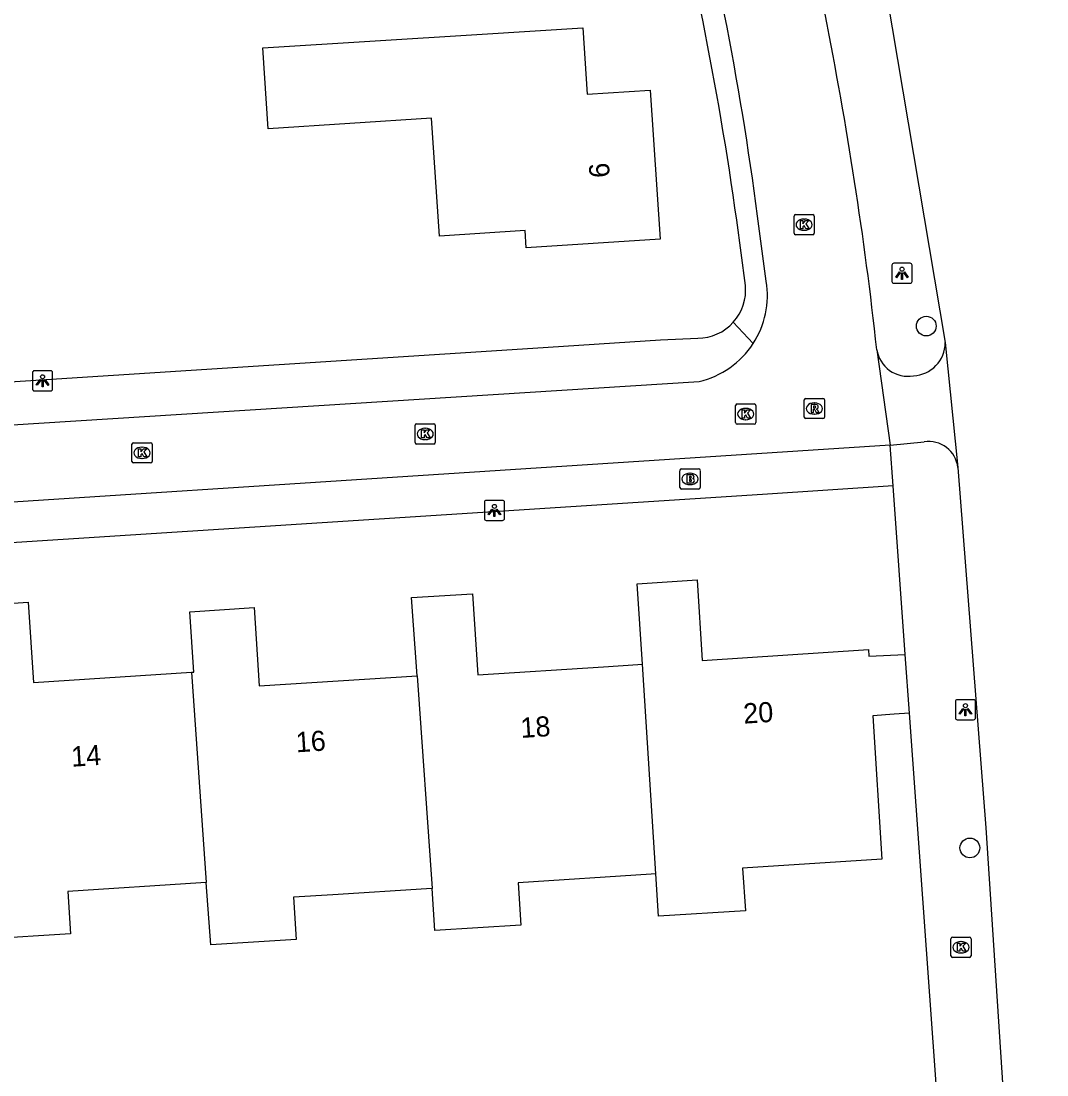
# Model space of a CAD drawing. Extents: x 159628 to 160723, y 388176 to 389416.
# Drawn here: x 160671.2 to 160722.1, y 388404.8 to 388457.1 of the extents above; entities that cross this region are included whole.
import ezdxf

# ---------------------------------------------------------------- set-up
doc = ezdxf.new("R2010")
doc.units = 0
for name, color, linetype in [('IMGEO_Boom', 7, 'Continuous'), ('IMGEO_Brandkraan', 7, 'Continuous'), ('IMGEO_Fietspad_gesloten', 7, 'Continuous'), ('IMGEO_Fietspad_open', 7, 'Continuous'), ('IMGEO_Kolk', 7, 'Continuous'), ('IMGEO_Lichtpunt', 7, 'Continuous'), ('IMGEO_Muur', 7, 'Continuous'), ('IMGEO_Pand', 7, 'Continuous'), ('IMGEO_Pand_nummerreeks', 7, 'Continuous'), ('IMGEO_Rijbaan_lokaal_open', 7, 'Continuous'), ('IMGEO_Rioolput', 7, 'Continuous'), ('IMGEO_Voetpad_open', 7, 'Continuous')]:
    doc.layers.add(name, color=color, linetype=linetype)

msp = doc.modelspace()

# ---------------------------------------------------------------- linework, layer by layer
at = {"layer": 'IMGEO_Boom'}
for centre in [(160716.092, 388441.932), (160718.25, 388416.067)]:
    msp.add_circle(centre, 0.489, dxfattribs=at)
at = {"layer": 'IMGEO_Brandkraan'}
for p, q in [((160703.883, 388433.931), (160703.883, 388434.783)), ((160703.958, 388434.857), (160704.81, 388434.857)), ((160704.371, 388434.637), (160704.396, 388434.637)), ((160704.884, 388434.783), (160704.884, 388433.931)), ((160704.394, 388434.077), (160704.369, 388434.077)), ((160704.81, 388433.857), (160703.958, 388433.857))]:
    msp.add_line(p, q, dxfattribs=at)
for points in [[(160703.883, 388433.931), (160703.883, 388434.783)], [(160703.958, 388434.857), (160704.81, 388434.857)], [(160704.231, 388434.557), (160704.231, 388434.157), (160704.444, 388434.157)], [(160704.462, 388434.557), (160704.231, 388434.557)], [(160704.41, 388434.476), (160704.356, 388434.476), (160704.356, 388434.4)], [(160704.356, 388434.4), (160704.409, 388434.4)], [(160704.884, 388434.783), (160704.884, 388433.931)], [(160704.418, 388434.324), (160704.356, 388434.324), (160704.356, 388434.243)], [(160704.356, 388434.243), (160704.418, 388434.243)], [(160704.81, 388433.857), (160703.958, 388433.857)]]:
    msp.add_lwpolyline(points, dxfattribs=at)
for centre, radius, start, end in [((160703.96, 388434.781), 0.0765, 91.552, 178.448), ((160703.96, 388434.781), 0.0765, 91.552, 178.448), ((160704.411, 388434.438), 0.0379, 267.8285, 90.9355), ((160704.466, 388434.412), 0.145, 59.4692, 91.5367), ((160704.491, 388434.459), 0.0922, 285.5137, 58.1501), ((160704.808, 388434.781), 0.0765, 1.552, 88.448), ((160704.808, 388434.781), 0.0765, 1.552, 88.448), ((160703.96, 388433.933), 0.0765, 181.552, 268.448), ((160703.96, 388433.933), 0.0765, 181.552, 268.448), ((160704.419, 388434.283), 0.0404, 269.8759, 90.5077), ((160704.45, 388434.408), 0.251, 268.6676, 293.5347), ((160704.496, 388434.267), 0.105, 301.3115, 78.989), ((160704.808, 388433.933), 0.0765, 271.552, 358.448), ((160704.808, 388433.933), 0.0765, 271.552, 358.448)]:
    msp.add_arc(centre, radius, start, end, dxfattribs=at)
for centre, major_axis, ratio, start_param, end_param in [((160704.37, 388434.357), (-0.387, 0.002), 0.722429, 4.712389, 7.853982), ((160704.395, 388434.357), (-0.39, 0.002), 0.717154, 1.570796, 4.712389)]:
    msp.add_ellipse(centre, major_axis=major_axis, ratio=ratio, start_param=start_param, end_param=end_param, dxfattribs=at)
at = {"layer": 'IMGEO_Fietspad_gesloten'}
for points in [[(160699.145, 388509.738), (160699.188, 388509.634), (160699.94, 388507.646), (160702.623, 388500), (160705.363, 388491.619), (160707.756, 388484.312), (160713.361, 388462.92), (160717.033, 388441.112)], [(160717.033, 388441.112), (160717.655, 388434.924)], [(160717.655, 388434.924), (160719.035, 388417.059), (160722.068, 388370.816)]]:
    msp.add_lwpolyline(points, dxfattribs=at)
at = {"layer": 'IMGEO_Fietspad_open'}
msp.add_lwpolyline([(160714.306, 388436.033), (160715.985, 388436.189)], dxfattribs=at)
for centre, radius, start, end in [((160715.179, 388441.004), 1.558, 188.8561, 280.0805), ((160715.384, 388441.118), 1.649, 272.3647, 359.8038), ((160716.228, 388434.775), 1.435, 5.9549, 99.7583)]:
    msp.add_arc(centre, radius, start, end, dxfattribs=at)
at = {"layer": 'IMGEO_Kolk'}
for p, q in [((160709.611, 388447.46), (160710.463, 388447.46)), ((160709.536, 388446.534), (160709.536, 388447.386)), ((160710.024, 388447.24), (160710.049, 388447.24)), ((160710.537, 388447.386), (160710.537, 388446.534)), ((160710.463, 388446.46), (160709.611, 388446.46)), ((160710.047, 388446.68), (160710.022, 388446.68)), ((160706.718, 388438.074), (160707.57, 388438.074)), ((160706.643, 388437.148), (160706.643, 388438)), ((160707.131, 388437.854), (160707.156, 388437.854)), ((160707.644, 388438), (160707.644, 388437.148)), ((160690.76, 388436.162), (160690.76, 388437.014)), ((160690.835, 388437.088), (160691.687, 388437.088)), ((160691.761, 388437.014), (160691.761, 388436.162)), ((160707.57, 388437.074), (160706.718, 388437.074)), ((160707.154, 388437.294), (160707.129, 388437.294)), ((160691.248, 388436.868), (160691.273, 388436.868)), ((160676.729, 388435.223), (160676.729, 388436.075)), ((160676.804, 388436.149), (160677.656, 388436.149)), ((160677.73, 388436.075), (160677.73, 388435.223)), ((160691.687, 388436.088), (160690.835, 388436.088)), ((160691.271, 388436.308), (160691.246, 388436.308)), ((160677.217, 388435.929), (160677.242, 388435.929)), ((160677.656, 388435.149), (160676.804, 388435.149)), ((160677.24, 388435.369), (160677.215, 388435.369)), ((160717.309, 388410.715), (160717.309, 388411.567)), ((160717.384, 388411.641), (160718.236, 388411.641)), ((160717.797, 388411.421), (160717.822, 388411.421)), ((160718.31, 388411.567), (160718.31, 388410.715)), ((160718.236, 388410.641), (160717.384, 388410.641)), ((160717.82, 388410.861), (160717.795, 388410.861))]:
    msp.add_line(p, q, dxfattribs=at)
for points in [[(160709.611, 388447.46), (160710.463, 388447.46)], [(160709.536, 388446.534), (160709.536, 388447.386)], [(160709.857, 388447.16), (160709.98, 388447.16), (160709.98, 388447.009), (160710.11, 388447.16), (160710.274, 388447.16), (160710.128, 388447.009), (160710.281, 388446.76), (160710.129, 388446.76), (160710.044, 388446.924), (160709.98, 388446.857), (160709.98, 388446.76), (160709.857, 388446.76), (160709.857, 388447.16)], [(160710.537, 388447.386), (160710.537, 388446.534)], [(160710.463, 388446.46), (160709.611, 388446.46)], [(160706.718, 388438.074), (160707.57, 388438.074)], [(160706.643, 388437.148), (160706.643, 388438)], [(160706.964, 388437.774), (160707.087, 388437.774), (160707.087, 388437.623), (160707.217, 388437.774), (160707.381, 388437.774), (160707.235, 388437.623), (160707.388, 388437.374), (160707.236, 388437.374), (160707.151, 388437.538), (160707.087, 388437.471), (160707.087, 388437.374), (160706.964, 388437.374), (160706.964, 388437.774)], [(160707.644, 388438), (160707.644, 388437.148)], [(160690.76, 388436.162), (160690.76, 388437.014)], [(160690.835, 388437.088), (160691.687, 388437.088)], [(160691.761, 388437.014), (160691.761, 388436.162)], [(160707.57, 388437.074), (160706.718, 388437.074)], [(160691.081, 388436.788), (160691.204, 388436.788), (160691.204, 388436.637), (160691.334, 388436.788), (160691.498, 388436.788), (160691.352, 388436.637), (160691.505, 388436.388), (160691.353, 388436.388), (160691.268, 388436.552), (160691.204, 388436.485), (160691.204, 388436.388), (160691.081, 388436.388), (160691.081, 388436.788)], [(160676.729, 388435.223), (160676.729, 388436.075)], [(160676.804, 388436.149), (160677.656, 388436.149)], [(160677.73, 388436.075), (160677.73, 388435.223)], [(160691.687, 388436.088), (160690.835, 388436.088)], [(160677.05, 388435.849), (160677.173, 388435.849), (160677.173, 388435.698), (160677.303, 388435.849), (160677.467, 388435.849), (160677.321, 388435.698), (160677.474, 388435.449), (160677.322, 388435.449), (160677.237, 388435.613), (160677.173, 388435.546), (160677.173, 388435.449), (160677.05, 388435.449), (160677.05, 388435.849)], [(160677.656, 388435.149), (160676.804, 388435.149)], [(160717.309, 388410.715), (160717.309, 388411.567)], [(160717.384, 388411.641), (160718.236, 388411.641)], [(160718.31, 388411.567), (160718.31, 388410.715)], [(160717.63, 388411.341), (160717.753, 388411.341), (160717.753, 388411.19), (160717.883, 388411.341), (160718.047, 388411.341), (160717.901, 388411.19), (160718.054, 388410.941), (160717.902, 388410.941), (160717.817, 388411.105), (160717.753, 388411.038), (160717.753, 388410.941), (160717.63, 388410.941), (160717.63, 388411.341)], [(160718.236, 388410.641), (160717.384, 388410.641)]]:
    msp.add_lwpolyline(points, dxfattribs=at)
for centre, start, end in [((160709.613, 388447.384), 91.552, 178.448), ((160709.613, 388447.384), 91.552, 178.448), ((160710.461, 388447.384), 1.552, 88.448), ((160710.461, 388447.384), 1.552, 88.448), ((160709.613, 388446.536), 181.552, 268.448), ((160709.613, 388446.536), 181.552, 268.448), ((160710.461, 388446.536), 271.552, 358.448), ((160710.461, 388446.536), 271.552, 358.448), ((160706.72, 388437.998), 91.552, 178.448), ((160706.72, 388437.998), 91.552, 178.448), ((160707.568, 388437.998), 1.552, 88.448), ((160707.568, 388437.998), 1.552, 88.448), ((160690.837, 388437.012), 91.552, 178.448), ((160690.837, 388437.012), 91.552, 178.448), ((160691.685, 388437.012), 1.552, 88.448), ((160691.685, 388437.012), 1.552, 88.448), ((160706.72, 388437.15), 181.552, 268.448), ((160706.72, 388437.15), 181.552, 268.448), ((160707.568, 388437.15), 271.552, 358.448), ((160707.568, 388437.15), 271.552, 358.448), ((160676.806, 388436.073), 91.552, 178.448), ((160676.806, 388436.073), 91.552, 178.448), ((160677.654, 388436.073), 1.552, 88.448), ((160677.654, 388436.073), 1.552, 88.448), ((160690.837, 388436.164), 181.552, 268.448), ((160690.837, 388436.164), 181.552, 268.448), ((160691.685, 388436.164), 271.552, 358.448), ((160691.685, 388436.164), 271.552, 358.448), ((160676.806, 388435.225), 181.552, 268.448), ((160676.806, 388435.225), 181.552, 268.448), ((160677.654, 388435.225), 271.552, 358.448), ((160677.654, 388435.225), 271.552, 358.448), ((160717.386, 388411.565), 91.552, 178.448), ((160717.386, 388411.565), 91.552, 178.448), ((160718.234, 388411.565), 1.552, 88.448), ((160718.234, 388411.565), 1.552, 88.448), ((160717.386, 388410.717), 181.552, 268.448), ((160717.386, 388410.717), 181.552, 268.448), ((160718.234, 388410.717), 271.552, 358.448), ((160718.234, 388410.717), 271.552, 358.448)]:
    msp.add_arc(centre, 0.0765, start, end, dxfattribs=at)
for centre, major_axis, ratio, start_param, end_param in [((160710.023, 388446.96), (-0.387, 0.002), 0.722429, 4.712389, 7.853982), ((160710.048, 388446.96), (-0.39, 0.002), 0.717154, 1.570796, 4.712389), ((160707.13, 388437.574), (-0.387, 0.002), 0.722429, 4.712389, 7.853982), ((160707.155, 388437.574), (-0.39, 0.002), 0.717154, 1.570796, 4.712389), ((160691.247, 388436.588), (-0.387, 0.002), 0.722429, 4.712389, 7.853982), ((160691.272, 388436.588), (-0.39, 0.002), 0.717154, 1.570796, 4.712389), ((160677.216, 388435.649), (-0.387, 0.002), 0.722429, 4.712389, 7.853982), ((160677.241, 388435.649), (-0.39, 0.002), 0.717154, 1.570796, 4.712389), ((160717.796, 388411.141), (-0.387, 0.002), 0.722429, 4.712389, 7.853982), ((160717.821, 388411.141), (-0.39, 0.002), 0.717154, 1.570796, 4.712389)]:
    msp.add_ellipse(centre, major_axis=major_axis, ratio=ratio, start_param=start_param, end_param=end_param, dxfattribs=at)
at = {"layer": 'IMGEO_Lichtpunt'}
for p, q in [((160714.39, 388444.956), (160714.39, 388444.149)), ((160714.39, 388444.956), (160714.39, 388444.149)), ((160715.292, 388445.051), (160714.484, 388445.051)), ((160715.292, 388445.051), (160714.484, 388445.051)), ((160715.386, 388444.149), (160715.386, 388444.956)), ((160715.386, 388444.149), (160715.386, 388444.956)), ((160714.484, 388444.055), (160715.292, 388444.055)), ((160714.484, 388444.055), (160715.292, 388444.055)), ((160671.803, 388439.623), (160671.803, 388438.816)), ((160671.803, 388439.623), (160671.803, 388438.816)), ((160672.705, 388439.718), (160671.897, 388439.718)), ((160672.705, 388439.718), (160671.897, 388439.718)), ((160672.799, 388438.816), (160672.799, 388439.623)), ((160672.799, 388438.816), (160672.799, 388439.623)), ((160671.897, 388438.722), (160672.705, 388438.722)), ((160671.897, 388438.722), (160672.705, 388438.722)), ((160694.194, 388433.199), (160694.194, 388432.392)), ((160694.194, 388433.199), (160694.194, 388432.392)), ((160695.096, 388433.294), (160694.288, 388433.294)), ((160695.096, 388433.294), (160694.288, 388433.294)), ((160695.19, 388432.392), (160695.19, 388433.199)), ((160695.19, 388432.392), (160695.19, 388433.199)), ((160694.288, 388432.298), (160695.096, 388432.298)), ((160694.288, 388432.298), (160695.096, 388432.298)), ((160717.533, 388423.32), (160717.533, 388422.513)), ((160717.533, 388423.32), (160717.533, 388422.513)), ((160718.435, 388423.415), (160717.627, 388423.415)), ((160718.435, 388423.415), (160717.627, 388423.415)), ((160718.529, 388422.513), (160718.529, 388423.32)), ((160718.529, 388422.513), (160718.529, 388423.32)), ((160717.627, 388422.419), (160718.435, 388422.419)), ((160717.627, 388422.419), (160718.435, 388422.419))]:
    msp.add_line(p, q, dxfattribs=at)
for points in [[(160714.764, 388444.62), (160714.803, 388444.592), (160714.615, 388444.33), (160714.577, 388444.357), (160714.764, 388444.62)], [(160714.866, 388444.572), (160714.913, 388444.572), (160714.913, 388444.25), (160714.866, 388444.25), (160714.866, 388444.572)], [(160714.976, 388444.592), (160715.014, 388444.619), (160715.201, 388444.357), (160715.162, 388444.329), (160714.976, 388444.592)], [(160672.177, 388439.287), (160672.216, 388439.259), (160672.028, 388438.997), (160671.99, 388439.024), (160672.177, 388439.287)], [(160672.279, 388439.239), (160672.326, 388439.239), (160672.326, 388438.917), (160672.279, 388438.917), (160672.279, 388439.239)], [(160672.389, 388439.259), (160672.427, 388439.286), (160672.614, 388439.024), (160672.575, 388438.996), (160672.389, 388439.259)], [(160694.568, 388432.863), (160694.607, 388432.835), (160694.419, 388432.573), (160694.381, 388432.6), (160694.568, 388432.863)], [(160694.78, 388432.835), (160694.818, 388432.862), (160695.005, 388432.6), (160694.966, 388432.572), (160694.78, 388432.835)], [(160694.67, 388432.815), (160694.717, 388432.815), (160694.717, 388432.493), (160694.67, 388432.493), (160694.67, 388432.815)], [(160717.907, 388422.984), (160717.946, 388422.956), (160717.758, 388422.694), (160717.72, 388422.721), (160717.907, 388422.984)], [(160718.009, 388422.936), (160718.056, 388422.936), (160718.056, 388422.614), (160718.009, 388422.614), (160718.009, 388422.936)], [(160718.119, 388422.956), (160718.157, 388422.983), (160718.344, 388422.721), (160718.305, 388422.693), (160718.119, 388422.956)]]:
    msp.add_lwpolyline(points, dxfattribs=at)
for centre in [(160714.889, 388444.754), (160672.302, 388439.421), (160694.693, 388432.997), (160718.032, 388423.118)]:
    msp.add_circle(centre, 0.0994, dxfattribs=at)
for centre, start, end in [((160714.484, 388444.956), 90, 180), ((160714.484, 388444.956), 90, 180), ((160715.292, 388444.956), 0, 90), ((160715.292, 388444.956), 0, 90), ((160714.484, 388444.149), 180, 270), ((160714.484, 388444.149), 180, 270), ((160715.292, 388444.149), 270, 0), ((160715.292, 388444.149), 270, 360), ((160671.897, 388439.623), 90, 180), ((160671.897, 388439.623), 90, 180), ((160672.705, 388439.623), 0, 90), ((160672.705, 388439.623), 0, 90), ((160671.897, 388438.816), 180, 270), ((160671.897, 388438.816), 180, 270), ((160672.705, 388438.816), 270, 0), ((160672.705, 388438.816), 270, 360), ((160694.288, 388433.199), 90, 180), ((160694.288, 388433.199), 90, 180), ((160695.096, 388433.199), 0, 90), ((160695.096, 388433.199), 0, 90), ((160694.288, 388432.392), 180, 270), ((160694.288, 388432.392), 180, 270), ((160695.096, 388432.392), 270, 0), ((160695.096, 388432.392), 270, 360), ((160717.627, 388423.32), 90, 180), ((160717.627, 388423.32), 90, 180), ((160718.435, 388423.32), 0, 90), ((160718.435, 388423.32), 0, 90), ((160717.627, 388422.513), 180, 270), ((160717.627, 388422.513), 180, 270), ((160718.435, 388422.513), 270, 0), ((160718.435, 388422.513), 270, 360)]:
    msp.add_arc(centre, 0.0946, start, end, dxfattribs=at)
at = {"layer": 'IMGEO_Muur'}
msp.add_lwpolyline([(160671.449, 388439.226), (160696.591, 388440.84)], dxfattribs=at)
at = {"layer": 'IMGEO_Pand'}
for points in [[(160683.224, 388455.725), (160694.084, 388456.401), (160699.074, 388456.714), (160699.28, 388453.43), (160702.409, 388453.624), (160702.9, 388446.249), (160696.265, 388445.808), (160696.208, 388446.677), (160691.968, 388446.395), (160691.579, 388452.243), (160683.488, 388451.712), (160683.224, 388455.725)], [(160702.026, 388425.172), (160701.77, 388429.163), (160704.732, 388429.353), (160704.989, 388425.36), (160713.23, 388425.907), (160713.251, 388425.573), (160715.045, 388425.652)], [(160690.862, 388424.598), (160690.591, 388428.473), (160693.598, 388428.661), (160693.863, 388424.647), (160700.098, 388425.048), (160701.796, 388425.157), (160702.026, 388425.172)], [(160668.574, 388424.05), (160668.294, 388428.04), (160671.596, 388428.256), (160671.856, 388424.265), (160679.681, 388424.775)], [(160679.681, 388424.775), (160679.79, 388424.782), (160679.596, 388427.776), (160682.79, 388427.984), (160683.033, 388424.108), (160690.862, 388424.598)], [(160715.253, 388422.753), (160715.045, 388425.652)], [(160702.693, 388414.774), (160702.026, 388425.172)], [(160679.681, 388424.775), (160680.415, 388414.348)], [(160690.862, 388424.598), (160691.599, 388414.063)], [(160715.253, 388422.753), (160714.506, 388422.695), (160713.44, 388422.611), (160713.894, 388415.511), (160706.989, 388415.068), (160707.125, 388412.953), (160702.828, 388412.678), (160702.693, 388414.774)], [(160702.693, 388414.774), (160702.451, 388414.758), (160695.865, 388414.335), (160696, 388412.24), (160691.746, 388411.967), (160691.599, 388414.063)], [(160680.415, 388414.348), (160680.137, 388414.33), (160673.551, 388413.907), (160673.686, 388411.812), (160669.451, 388411.541), (160669.304, 388413.636)], [(160691.599, 388414.063), (160691.326, 388414.045), (160686.685, 388413.747), (160684.74, 388413.622), (160684.875, 388411.527), (160680.633, 388411.255), (160680.415, 388414.348)]]:
    msp.add_lwpolyline(points, dxfattribs=at)
at = {"layer": 'IMGEO_Rijbaan_lokaal_open'}
for points in [[(160708.162, 388444.153), (160707.726, 388447.388)], [(160713.64, 388440.764), (160714.306, 388436.033)], [(160644.887, 388435.407), (160704.837, 388439.183)], [(160714.306, 388436.033), (160645.126, 388431.536)]]:
    msp.add_lwpolyline(points, dxfattribs=at)
for centre, radius, start, end in [((160559.845, 388428.347), 149.102, 7.33718, 15.11149), ((160522.582, 388419.788), 192.206, 6.26539, 11.28182), ((160703.83, 388443.455), 4.388, 326.9785, 9.1489), ((160703.827, 388443.456), 4.39, 283.2972, 326.9914)]:
    msp.add_arc(centre, radius, start, end, dxfattribs=at)
at = {"layer": 'IMGEO_Rioolput'}
for p, q in [((160710.044, 388437.42), (160710.044, 388438.272)), ((160710.119, 388438.346), (160710.971, 388438.346)), ((160710.532, 388438.126), (160710.557, 388438.126)), ((160711.045, 388438.272), (160711.045, 388437.42)), ((160710.555, 388437.566), (160710.53, 388437.566)), ((160710.971, 388437.346), (160710.119, 388437.346))]:
    msp.add_line(p, q, dxfattribs=at)
for points in [[(160710.044, 388437.42), (160710.044, 388438.272)], [(160710.119, 388438.346), (160710.971, 388438.346)], [(160711.045, 388438.272), (160711.045, 388437.42)], [(160710.633, 388438.044), (160710.381, 388438.046), (160710.381, 388437.646)], [(160710.381, 388437.646), (160710.505, 388437.646), (160710.505, 388437.808), (160710.516, 388437.808)], [(160710.559, 388437.965), (160710.505, 388437.965), (160710.505, 388437.884)], [(160710.505, 388437.884), (160710.557, 388437.884)], [(160710.563, 388437.779), (160710.634, 388437.646), (160710.774, 388437.646), (160710.709, 388437.772)], [(160710.971, 388437.346), (160710.119, 388437.346)]]:
    msp.add_lwpolyline(points, dxfattribs=at)
for centre, radius, start, end in [((160710.121, 388438.27), 0.0765, 91.552, 178.448), ((160710.121, 388438.27), 0.0765, 91.552, 178.448), ((160710.969, 388438.27), 0.0765, 1.552, 88.448), ((160710.969, 388438.27), 0.0765, 1.552, 88.448), ((160710.515, 388437.755), 0.0533, 26.0293, 88.6989), ((160710.541, 388438.073), 0.19, 274.7715, 282.9687), ((160710.565, 388437.869), 0.0964, 77.0061, 93.1865), ((160710.579, 388437.926), 0.0378, 276.6634, 79.6772), ((160710.632, 388437.934), 0.109, 350.3612, 89.416), ((160710.63, 388437.934), 0.112, 277.5842, 350.9817), ((160710.614, 388437.719), 0.108, 29.5134, 73.7905), ((160710.121, 388437.422), 0.0765, 181.552, 268.448), ((160710.121, 388437.422), 0.0765, 181.552, 268.448), ((160710.969, 388437.422), 0.0765, 271.552, 358.448), ((160710.969, 388437.422), 0.0765, 271.552, 358.448)]:
    msp.add_arc(centre, radius, start, end, dxfattribs=at)
for centre, major_axis, ratio, start_param, end_param in [((160710.531, 388437.846), (-0.387, 0.002), 0.722429, 4.712389, 7.853982), ((160710.556, 388437.846), (-0.39, 0.002), 0.717154, 1.570796, 4.712389)]:
    msp.add_ellipse(centre, major_axis=major_axis, ratio=ratio, start_param=start_param, end_param=end_param, dxfattribs=at)
at = {"layer": 'IMGEO_Voetpad_open'}
for points in [[(160707.131, 388443.953), (160706.701, 388447.179)], [(160707.509, 388441.064), (160706.527, 388442.124)], [(160602.65, 388434.91), (160608.111, 388435.159), (160609.972, 388435.278), (160631.195, 388436.641), (160671.449, 388439.226), (160696.591, 388440.84), (160702.923, 388441.247), (160704.774, 388441.328)], [(160714.448, 388434.009), (160714.306, 388436.033)], [(160714.448, 388434.009), (160707.968, 388433.592), (160604, 388426.895), (160601.214, 388426.719), (160595.247, 388426.341)], [(160715.045, 388425.652), (160714.448, 388434.009)], [(160716.764, 388401.841), (160715.253, 388422.753)]]:
    msp.add_lwpolyline(points, dxfattribs=at)
for centre, radius, start, end in [((160534.59, 388422.958), 173.807, 8.01051, 14.64511), ((160704.747, 388443.726), 2.394, 318.0074, 5.4425), ((160704.74, 388443.732), 2.404, 270.8166, 318.027)]:
    msp.add_arc(centre, radius, start, end, dxfattribs=at)

# ---------------------------------------------------------------- texts
at = {"layer": 'IMGEO_Pand_nummerreeks'}
for s, rotation, p in [('9', 273.8089, (160699.363, 388449.993)), ('20', 3.6669, (160707.053, 388422.224)), ('18', 3.6669, (160696.011, 388421.516)), ('16', 3.6669, (160684.877, 388420.802)), ('14', 3.6669, (160673.746, 388420.089))]:
    msp.add_text(s, height=1, rotation=rotation, dxfattribs=at).set_placement(p)

doc.saveas('drawing.dxf')
